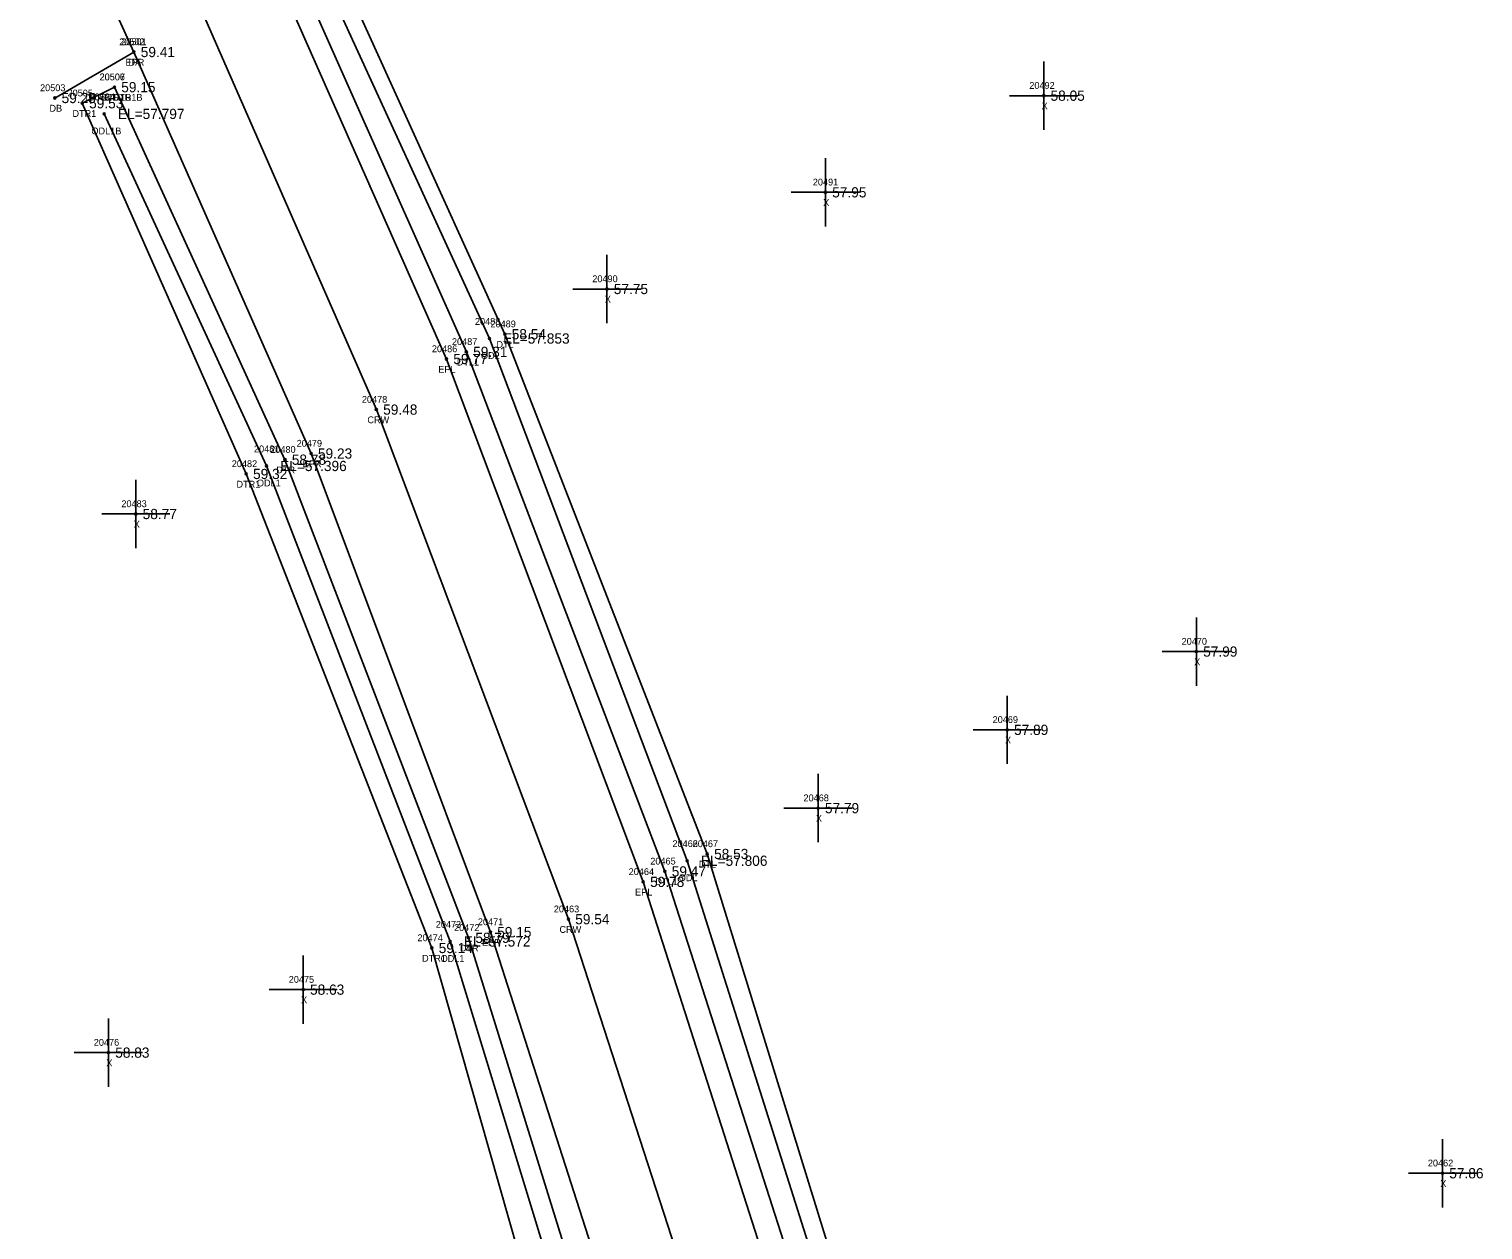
# Model space of a CAD drawing. Extents: x 2396547 to 2397655, y 770185 to 772649.
# Drawn here: x 2397425.8 to 2397638.9, y 770379.1 to 770555.1 of the extents above; entities that cross this region are included whole.
import ezdxf

# ---------------------------------------------------------------- set-up
doc = ezdxf.new("R2010")
doc.units = 0
for name, color, linetype in [('RD_DTM_BkLn1', 7, 'Continuous'), ('RD_EX_Driveway', 7, 'Continuous'), ('RD_EX_Driveway_txCode', 7, 'Continuous'), ('RD_EX_H2O', 7, 'Continuous'), ('RD_EX_H2O_txCode', 7, 'Continuous'), ('RD_EX_Misc', 7, 'Continuous'), ('RD_EX_Misc_txCode', 7, 'Continuous'), ('RD_EX_Road', 7, 'Continuous'), ('RD_EX_Road_txCode', 7, 'Continuous'), ('RD_EX_TX_Driveway_ELEV', 7, 'Continuous'), ('RD_EX_TX_H2O_ELEV', 7, 'Continuous'), ('RD_EX_TX_Misc_ELEV', 7, 'Continuous'), ('RD_EX_TX_Road_ELEV', 7, 'Continuous'), ('RD_HC_Survey_ELEV', 7, 'Continuous'), ('RD_HC_Survey_txCode', 7, 'Continuous'), ('RD_SMD_Locator', 7, 'Continuous')]:
    doc.layers.add(name, color=color, linetype=linetype)

msp = doc.modelspace()

# ---------------------------------------------------------------- linework, layer by layer
at = {"layer": 'RD_DTM_BkLn1'}
msp.add_lwpolyline([(2397565.46, 770206.19), (2397547.69, 770280.33), (2397528.11, 770352.94), (2397504.84, 770424.66), (2397476.69, 770499.34), (2397447.19, 770566.69), (2397412.23, 770635.13), (2397363.03, 770719.95), (2397270.14, 770871.5)], dxfattribs=at)
at = {"layer": 'RD_EX_Driveway'}
msp.add_line((2397441.16, 770551.74), (2397429.56, 770545), dxfattribs=at)
at = {"layer": 'RD_EX_H2O'}
for points in [[(2397586.15, 770211.51), (2397567.31, 770287.61), (2397548.79, 770357.79), (2397525.19, 770434.22), (2397495.53, 770510.39), (2397465.51, 770576.5), (2397430.55, 770645.5), (2397380.29, 770734.7), (2397327.01, 770824.44), (2397291.42, 770882.36)], [(2397583.73, 770210.91), (2397565.2, 770287.05), (2397546.34, 770357.13), (2397522.25, 770433.23), (2397493.26, 770509.76), (2397463.19, 770575.43), (2397428.34, 770644.33), (2397377.24, 770732.42), (2397321.77, 770821.7), (2397287.01, 770879.96)], [(2397579.43, 770209.93), (2397561.1, 770285.3), (2397543.19, 770356.19), (2397518.98, 770431.67), (2397489.88, 770507.8), (2397460.56, 770573.86), (2397425.02, 770642.83), (2397373.6, 770730.3), (2397319.08, 770819.92), (2397284.14, 770878.8)], [(2397544.21, 770204.98), (2397524.44, 770279.37), (2397505.98, 770346.02), (2397484.83, 770420.44), (2397457.62, 770489.91), (2397433.59, 770544.23), (2397438.3, 770546.59)], [(2397549.62, 770204.86), (2397531.98, 770280.53), (2397513.08, 770348.26), (2397490.2, 770421.93), (2397463.3, 770492), (2397438.3, 770546.59)], [(2397547.08, 770204.83), (2397528.51, 770280.48), (2397510.07, 770347.55), (2397487.52, 770421.4), (2397460.59, 770491.08), (2397436.81, 770542.67)]]:
    msp.add_lwpolyline(points, dxfattribs=at)
at = {"layer": 'RD_EX_Misc'}
for p, q in [((2397574.5, 770540.34), (2397574.5, 770550.34)), ((2397569.5, 770545.34), (2397579.5, 770545.34)), ((2397542.5, 770526.18), (2397542.5, 770536.18)), ((2397537.5, 770531.18), (2397547.5, 770531.18)), ((2397510.49, 770512.01), (2397510.49, 770522.01)), ((2397505.49, 770517.01), (2397515.49, 770517.01)), ((2397441.44, 770479.04), (2397441.44, 770489.04)), ((2397436.44, 770484.04), (2397446.44, 770484.04)), ((2397596.87, 770458.88), (2397596.87, 770468.88)), ((2397591.87, 770463.88), (2397601.87, 770463.88)), ((2397569.15, 770447.41), (2397569.15, 770457.41)), ((2397564.15, 770452.41), (2397574.15, 770452.41)), ((2397541.43, 770435.94), (2397541.43, 770445.94)), ((2397536.43, 770440.94), (2397546.43, 770440.94)), ((2397465.97, 770409.34), (2397465.97, 770419.34)), ((2397460.97, 770414.34), (2397470.97, 770414.34)), ((2397437.42, 770400.11), (2397437.42, 770410.11)), ((2397432.42, 770405.11), (2397442.42, 770405.11)), ((2397632.94, 770382.43), (2397632.94, 770392.43)), ((2397627.94, 770387.43), (2397637.94, 770387.43))]:
    msp.add_line(p, q, dxfattribs=at)
at = {"layer": 'RD_EX_Road'}
for points in [[(2397576.88, 770209.21), (2397558.85, 770284.47), (2397539.93, 770354.87), (2397515.81, 770430.13), (2397486.97, 770506.75), (2397457.82, 770572.7), (2397422.37, 770641.75), (2397371.16, 770729.12), (2397316.57, 770818.52), (2397280.76, 770876.73)], [(2397553.19, 770205.48), (2397535.12, 770280.96), (2397517, 770349.24), (2397493.4, 770422.78), (2397467.13, 770492.9), (2397441.16, 770551.74), (2397436.66, 770561.67), (2397402.21, 770629.28), (2397353, 770712.83), (2397296, 770806.32), (2397260.16, 770864.73)]]:
    msp.add_lwpolyline(points, dxfattribs=at)
at = {"layer": 'RD_SMD_Locator'}
for centre in [(2397441.16, 770551.74), (2397441.16, 770551.74), (2397438.3, 770546.59), (2397438.3, 770546.59), (2397429.56, 770545), (2397574.5, 770545.34), (2397433.59, 770544.23), (2397436.81, 770542.67), (2397542.5, 770531.18), (2397510.49, 770517.01), (2397495.53, 770510.39), (2397493.26, 770509.76), (2397486.97, 770506.75), (2397489.88, 770507.8), (2397476.69, 770499.34), (2397460.59, 770491.08), (2397463.3, 770492), (2397467.13, 770492.9), (2397457.62, 770489.91), (2397441.44, 770484.04), (2397596.87, 770463.88), (2397569.15, 770452.41), (2397541.43, 770440.94), (2397525.19, 770434.22), (2397518.98, 770431.67), (2397522.25, 770433.23), (2397515.81, 770430.13), (2397504.84, 770424.66), (2397487.52, 770421.4), (2397490.2, 770421.93), (2397493.4, 770422.78), (2397484.83, 770420.44), (2397465.97, 770414.34), (2397437.42, 770405.11), (2397632.94, 770387.43)]:
    msp.add_circle(centre, 0.15, dxfattribs=at)

# ---------------------------------------------------------------- texts
at = {"layer": 'RD_EX_Driveway_txCode'}
for s, p in [('20502', (2397439.01, 770552.74)), ('DA', (2397440.37, 770549.74)), ('20503', (2397427.4, 770546)), ('DB', (2397428.78, 770543))]:
    msp.add_text(s, height=1, dxfattribs=at).set_placement(p)
at = {"layer": 'RD_EX_H2O_txCode'}
for s, p in [('20506', (2397436.12, 770547.59)), ('20507', (2397436.14, 770547.59)), ('20505', (2397431.43, 770545.23)), ('DTRB DTR1B', (2397434.02, 770544.59)), ('20504', (2397434.66, 770544.67)), ('DTR1B', (2397436.4, 770544.59)), ('DTR1', (2397432.15, 770542.23)), ('ODL1B', (2397434.93, 770539.67)), ('20488', (2397491.14, 770511.76)), ('20489', (2397493.41, 770511.39)), ('20487', (2397487.77, 770508.8)), ('DTL', (2397494.29, 770508.39)), ('DTL1', (2397488.48, 770505.8)), ('ODL', (2397492.02, 770506.76)), ('20481', (2397458.76, 770493.08)), ('20480', (2397461.14, 770493)), ('20482', (2397455.5, 770490.91)), ('ODL1', (2397459.18, 770488.08)), ('DTR', (2397462.03, 770490)), ('DTR1', (2397456.19, 770487.91)), ('20466', (2397520.09, 770435.23)), ('20467', (2397523.05, 770435.22)), ('20465', (2397516.84, 770432.67)), ('DTL', (2397523.95, 770432.22)), ('DTL1', (2397517.57, 770429.67)), ('ODL', (2397521.01, 770430.23)), ('20473', (2397485.4, 770423.4)), ('20472', (2397488.08, 770422.93)), ('20474', (2397482.71, 770421.44)), ('DTR', (2397488.93, 770419.93)), ('DTR1', (2397483.39, 770418.44)), ('ODL1', (2397486.11, 770418.4))]:
    msp.add_text(s, height=1, dxfattribs=at).set_placement(p)
at = {"layer": 'RD_EX_Misc_txCode'}
for s, p in [('20492', (2397572.39, 770546.34)), ('X', (2397574.19, 770543.34)), ('20491', (2397540.66, 770532.18)), ('X', (2397542.18, 770529.18)), ('20490', (2397508.34, 770518.01)), ('X', (2397510.18, 770515.01)), ('20483', (2397439.32, 770485.04)), ('X', (2397441.13, 770482.04)), ('20470', (2397594.71, 770464.88)), ('X', (2397596.55, 770461.88)), ('20469', (2397567.01, 770453.41)), ('X', (2397568.83, 770450.41)), ('20468', (2397539.29, 770441.94)), ('X', (2397541.11, 770438.94)), ('20475', (2397463.85, 770415.34)), ('X', (2397465.65, 770412.34)), ('20476', (2397435.28, 770406.11)), ('X', (2397437.11, 770403.11)), ('20462', (2397630.8, 770388.43)), ('X', (2397632.62, 770385.43))]:
    msp.add_text(s, height=1, dxfattribs=at).set_placement(p)
at = {"layer": 'RD_EX_Road_txCode'}
for s, p in [('20501', (2397439.29, 770552.74)), ('EPR', (2397439.93, 770549.74)), ('20486', (2397484.83, 770507.75)), ('EPL', (2397485.77, 770504.75)), ('20479', (2397465.01, 770493.9)), ('EPR', (2397465.9, 770490.9)), ('20464', (2397513.67, 770431.13)), ('EPL', (2397514.61, 770428.13)), ('20471', (2397491.57, 770423.78)), ('EPR', (2397492.17, 770420.78))]:
    msp.add_text(s, height=1, dxfattribs=at).set_placement(p)
at = {"layer": 'RD_EX_TX_Driveway_ELEV'}
for s, p in [('59.41', (2397442.16, 770550.99)), ('59.25', (2397430.56, 770544.25))]:
    msp.add_text(s, height=1.5, dxfattribs=at).set_placement(p)
at = {"layer": 'RD_EX_TX_H2O_ELEV'}
for s, p in [('59.15', (2397439.3, 770545.84)), ('59.15', (2397439.3, 770545.84)), ('59.53', (2397434.59, 770543.48)), ('EL=57.797', (2397438.81, 770541.92)), ('EL=57.853', (2397495.26, 770509.01)), ('58.54', (2397496.53, 770509.64)), ('59.31', (2397490.88, 770507.05)), ('EL=57.396', (2397462.59, 770490.33)), ('58.78', (2397464.3, 770491.25)), ('59.32', (2397458.62, 770489.16)), ('EL=57.806', (2397524.25, 770432.48)), ('58.53', (2397526.19, 770433.47)), ('59.47', (2397519.98, 770430.92)), ('59.14', (2397485.83, 770419.69)), ('EL=57.572', (2397489.52, 770420.65)), ('58.79', (2397491.2, 770421.18))]:
    msp.add_text(s, height=1.5, dxfattribs=at).set_placement(p)
at = {"layer": 'RD_EX_TX_Misc_ELEV'}
for s, p in [('58.05', (2397575.5, 770544.59)), ('57.95', (2397543.5, 770530.43)), ('57.75', (2397511.49, 770516.26)), ('58.77', (2397442.44, 770483.29)), ('57.99', (2397597.87, 770463.13)), ('57.89', (2397570.15, 770451.66)), ('57.79', (2397542.43, 770440.19)), ('58.63', (2397466.97, 770413.59)), ('58.83', (2397438.42, 770404.36)), ('57.86', (2397633.94, 770386.68))]:
    msp.add_text(s, height=1.5, dxfattribs=at).set_placement(p)
at = {"layer": 'RD_EX_TX_Road_ELEV'}
for s, p in [('59.41', (2397442.16, 770550.99)), ('59.77', (2397487.97, 770506)), ('59.23', (2397468.13, 770492.15)), ('59.78', (2397516.81, 770429.38)), ('59.15', (2397494.4, 770422.03))]:
    msp.add_text(s, height=1.5, dxfattribs=at).set_placement(p)
at = {"layer": 'RD_HC_Survey_ELEV'}
for s, p in [('59.48', (2397477.69, 770498.59)), ('59.54', (2397505.84, 770423.91))]:
    msp.add_text(s, height=1.5, dxfattribs=at).set_placement(p)
at = {"layer": 'RD_HC_Survey_txCode'}
for s, p in [('20478', (2397474.57, 770500.34)), ('CRW', (2397475.38, 770497.34)), ('20463', (2397502.7, 770425.66)), ('CRW', (2397503.53, 770422.66))]:
    msp.add_text(s, height=1, dxfattribs=at).set_placement(p)

doc.saveas('drawing.dxf')
